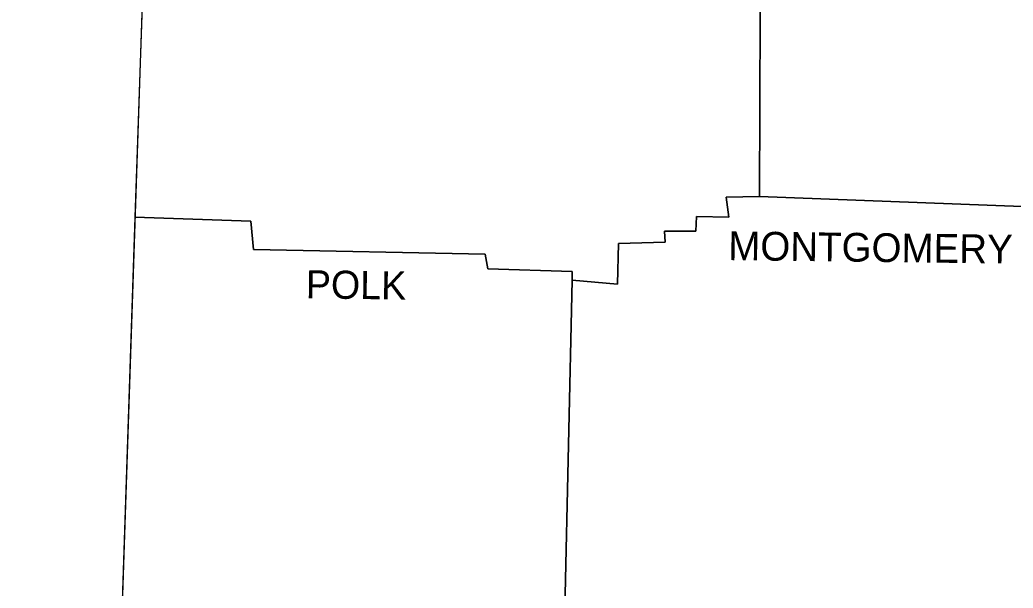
# Model space of a CAD drawing. Extents: x -28335 to 1228743, y -22428 to 152440.
# Drawn here: x 24268 to 27629, y 10013 to 11936 of the extents above; entities that cross this region are included whole.
import ezdxf

# ---------------------------------------------------------------- set-up
doc = ezdxf.new("R2010")
doc.units = 0
doc.layers.add('16', color=7, linetype='Continuous')
doc.layers.add('8', color=7, linetype='Continuous')

msp = doc.modelspace()

# ---------------------------------------------------------------- linework, layer by layer
at = {"layer": '16'}
for p, q in [((26774.6, 12266.1), (26771.5, 11338.2)), ((24681.7, 11985.7), (24657.9, 11268)), ((26771.5, 11338.2), (27659.5, 11304.3)), ((27659.5, 11304.3), (26771.5, 11338.2)), ((24657.9, 11268), (24596, 9400.7)), ((26558.5, 11270.3), (26556.3, 11220.4)), ((26667.3, 11268), (26558.5, 11270.3)), ((26293.5, 11179.7), (26291.2, 11041.5)), ((26452.1, 11184.2), (26293.5, 11179.7))]:
    msp.add_line(p, q, dxfattribs=at)
for points in [[(26137.2, 11055.1), (26291.2, 11041.5), (26293.5, 11179.7), (26452.1, 11184.2), (26449.8, 11220.4), (26556.3, 11220.4), (26558.5, 11270.3), (26667.3, 11268), (26658.2, 11336), (26771.5, 11338.2), (26774.6, 12266.1)], [(26771.5, 11338.2), (26658.2, 11336), (26667.3, 11268)], [(26137.2, 11055.1), (26137.2, 11084.5), (25851.7, 11093.6), (25842.7, 11143.4), (25058.9, 11159.3), (25049.8, 11254.4), (24657.9, 11268)], [(24657.9, 11268), (25049.8, 11254.4), (25058.9, 11159.3), (25842.7, 11143.4), (25851.7, 11093.6)], [(26556.3, 11220.4), (26449.8, 11220.4), (26452.1, 11184.2)], [(25851.7, 11093.6), (26137.2, 11084.5), (26137.2, 11055.1)], [(24596, 9400.7), (25249.2, 9372), (25251.4, 9662), (25219.7, 9684.6), (25240.1, 9942.8), (26112.3, 9940.6), (26137.2, 11055.1)], [(26291.2, 11041.5), (26137.2, 11055.1), (26112.3, 9940.6)]]:
    msp.add_lwpolyline(points, dxfattribs=at)
at = {"layer": '8'}
for points in [[(24268.3, 17422.7), (24737.2, 13657.8), (24533.3, 7512.2)], [(26774.6, 12266.1), (26771.5, 11338.2), (26658.2, 11336), (26667.3, 11268), (26558.5, 11270.3), (26556.3, 11220.4), (26449.8, 11220.4), (26452.1, 11184.2), (26293.5, 11179.7), (26291.2, 11041.5), (26137.2, 11055.1), (26112.3, 9940.6), (25240.1, 9942.8), (25219.7, 9684.6), (25251.4, 9662), (25249.2, 9372), (24596, 9400.7)], [(27659.5, 11304.3), (26771.5, 11338.2)], [(24657.9, 11268), (25049.8, 11254.4), (25058.9, 11159.3), (25842.7, 11143.4), (25851.7, 11093.6), (26137.2, 11084.5), (26137.2, 11055.1)]]:
    msp.add_lwpolyline(points, dxfattribs=at)

# ---------------------------------------------------------------- texts
for s, height, rotation, p in [('MONTGOMERY', 97.42, 359.2944, (26665, 11123)), ('POLK', 95.13, 359.2152, (25235.6, 10993.9))]:
    msp.add_text(s, height=height, rotation=rotation, dxfattribs=at).set_placement(p)

doc.saveas('drawing.dxf')
